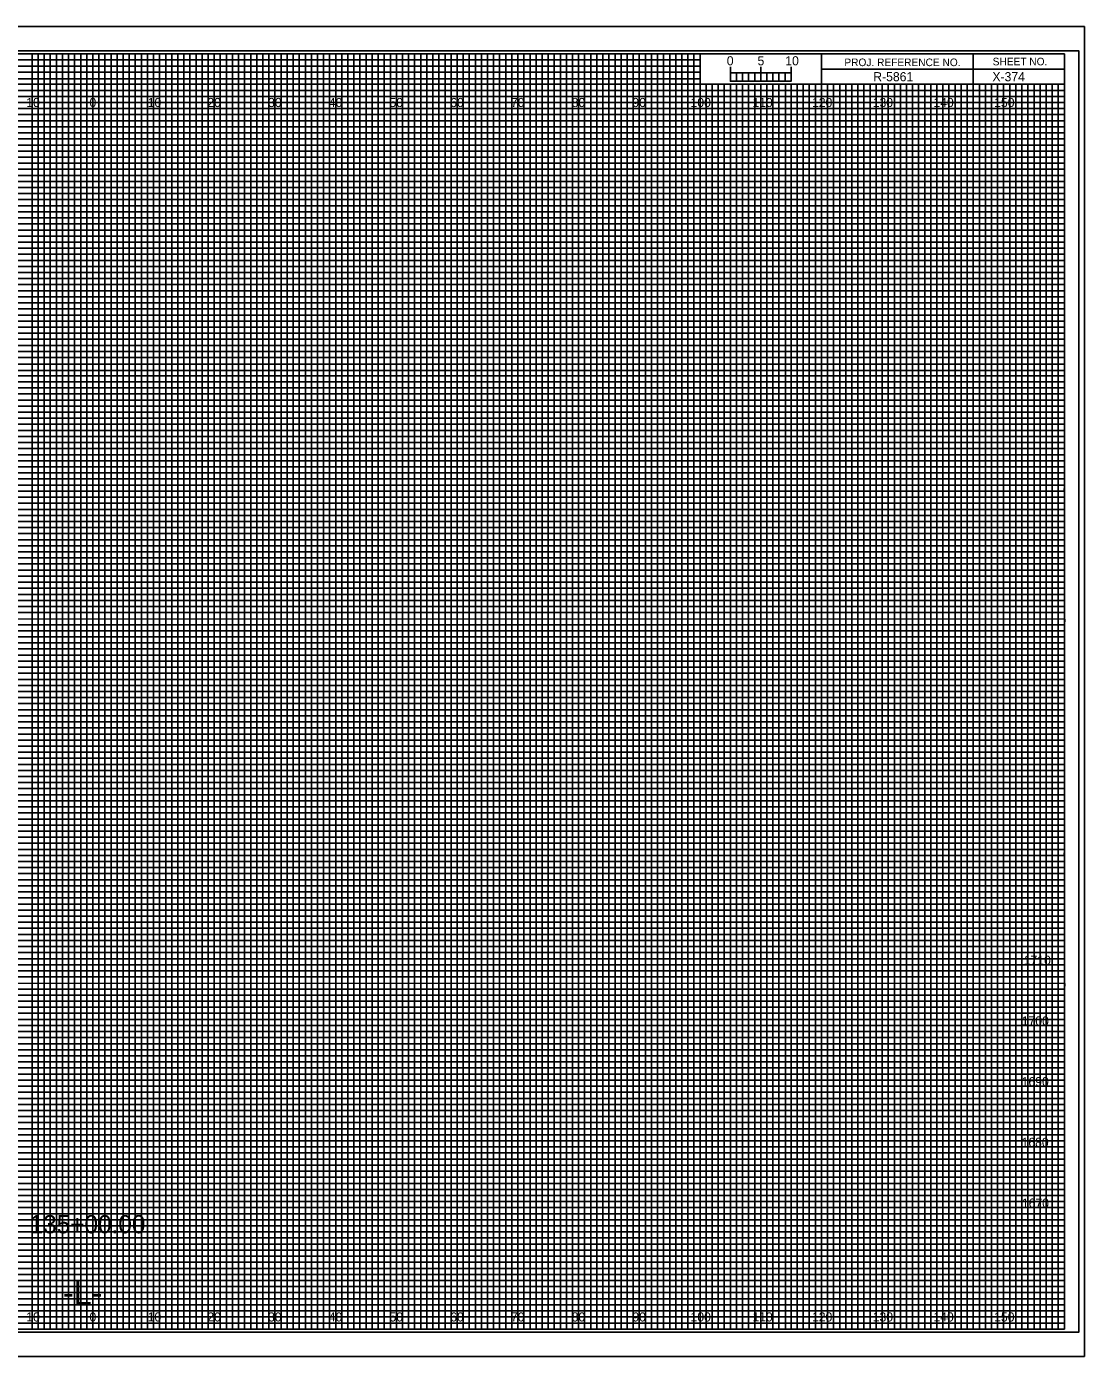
# Model space of a CAD drawing. Extents: x -13 to 323, y -5 to 2414.
# Drawn here: x 149.1 to 323.3, y 2195.5 to 2414.5 of the extents above; entities that cross this region are included whole.
import ezdxf

# ---------------------------------------------------------------- set-up
doc = ezdxf.new("R2010")
doc.units = 0
for name, color, linetype in [('Prop XS Alignment Label', 7, 'Continuous'), ('Prop XS Bar Scale Labels', 7, 'Continuous'), ('Prop XS Elevation Labels', 7, 'Continuous'), ('Prop XS Offset Labels', 7, 'Continuous'), ('Prop XS Project Number', 7, 'Continuous'), ('Prop XS Sheet Number', 7, 'Continuous'), ('Prop XS Station Labels', 7, 'Continuous'), ('Sheet Cross Section CELL', 7, 'Continuous'), ('Sheet Cross Section Grid Major CELL', 7, 'Continuous'), ('Sheet Cross Section Grid Middle CELL', 7, 'Continuous'), ('Sheet Cross Section Grid Minor 1 CELL', 7, 'Continuous'), ('Sheet Cross Section Grid Minor 2 CELL', 7, 'Continuous'), ('Sheet Cross Section Scale CELL', 7, 'Continuous'), ('Sheet Cutting Line CELL', 7, 'Continuous'), ('Sheet DOT Grid CELL', 7, 'Continuous'), ('Sheet Plot Border Inside CELL', 7, 'Continuous'), ('Sheet Plot Border Outside CELL', 7, 'Continuous')]:
    doc.layers.add(name, color=color, linetype=linetype)

msp = doc.modelspace()

# ---------------------------------------------------------------- linework, layer by layer
at = {"layer": 'Sheet Cross Section CELL'}
for p, q in [((305, 2410), (305, 2405)), ((305, 2405), (305, 2410)), ((280, 2407.5), (280, 2405)), ((320, 2407.49), (280, 2407.49)), ((280, 2405), (320, 2405))]:
    msp.add_line(p, q, dxfattribs=at)
for points in [[(320, 2410), (0, 2410), (0, 2200), (320, 2200)], [(280, 2410), (260, 2410), (260, 2405.03), (280, 2405.03)], [(320, 2410), (280, 2410), (280, 2405), (320, 2405)]]:
    msp.add_lwpolyline(points, close=True, dxfattribs=at)
at = {"layer": 'Sheet Cross Section Grid Major CELL'}
for p, q in [((150, 2410), (140, 2410)), ((150, 2200), (150, 2410)), ((170, 2410), (160, 2410)), ((160, 2410), (160, 2200)), ((170, 2200), (170, 2410)), ((190, 2410), (180, 2410)), ((180, 2410), (180, 2200)), ((190, 2200), (190, 2410)), ((210, 2410), (200, 2410)), ((200, 2410), (200, 2200)), ((210, 2200), (210, 2410)), ((230, 2410), (220, 2410)), ((220, 2410), (220, 2200)), ((230, 2200), (230, 2410)), ((250, 2410), (240, 2410)), ((240, 2410), (240, 2200)), ((250, 2200), (250, 2410)), ((260, 2410), (260, 2200)), ((270, 2200), (270, 2405)), ((290, 2405), (280, 2405)), ((280, 2405), (280, 2200)), ((290, 2200), (290, 2405)), ((310, 2405), (300, 2405)), ((300, 2405), (300, 2200)), ((310, 2200), (310, 2405)), ((160, 2200), (150, 2200)), ((180, 2200), (170, 2200)), ((200, 2200), (190, 2200)), ((220, 2200), (210, 2200)), ((240, 2200), (230, 2200)), ((260, 2200), (250, 2200)), ((280, 2200), (270, 2200)), ((300, 2200), (290, 2200)), ((320, 2200), (310, 2200)), ((320, 2200), (320, 2200))]:
    msp.add_line(p, q, dxfattribs=at)
for points in [[(0, 2400), (320, 2400), (320, 2390), (0, 2390)], [(0, 2380), (320, 2380), (320, 2370), (0, 2370)], [(0, 2360), (320, 2360), (320, 2350), (0, 2350)], [(0, 2340), (320, 2340), (320, 2330), (0, 2330)], [(0, 2320), (320, 2320), (320, 2310), (0, 2310)], [(0, 2300), (320, 2300), (320, 2290), (0, 2290)], [(0, 2280), (320, 2280), (320, 2270), (0, 2270)], [(0, 2260), (320, 2260), (320, 2250), (0, 2250)], [(0, 2240), (320, 2240), (320, 2230), (0, 2230)], [(0, 2220), (320, 2220), (320, 2210), (0, 2210)]]:
    msp.add_lwpolyline(points, dxfattribs=at)
at = {"layer": 'Sheet Cross Section Grid Middle CELL'}
for points in [[(145, 2200), (155, 2200), (155, 2410), (165, 2410), (165, 2200), (175, 2200), (175, 2410), (185, 2410), (185, 2200), (195, 2200), (195, 2410), (205, 2410), (205, 2200), (215, 2200), (215, 2410), (225, 2410), (225, 2200), (235, 2200), (235, 2410), (245, 2410), (245, 2200), (255, 2200), (255, 2410), (259.93, 2410), (260, 2410), (260, 2405), (264.99, 2405), (264.99, 2200), (275, 2200), (275, 2405), (285, 2405), (285, 2200), (295, 2200), (295, 2405), (305, 2405), (305, 2200), (315, 2200), (315, 2405)], [(0, 2405), (275, 2405)], [(0, 2385), (320, 2385), (320, 2395), (0, 2395)], [(0, 2365), (320, 2365), (320, 2375), (0, 2375)], [(0, 2345), (320, 2345), (320, 2355), (0, 2355)], [(0, 2325), (320, 2325), (320, 2335), (0, 2335)], [(0, 2305), (320, 2305), (320, 2315), (0, 2315)], [(0, 2285), (320, 2285), (320, 2295), (0, 2295)], [(0, 2265), (320, 2265), (320, 2275), (0, 2275)], [(0, 2245), (320, 2245), (320, 2255), (0, 2255)], [(0, 2225), (320, 2225), (320, 2235), (0, 2235)], [(0, 2205), (320, 2205), (320, 2215), (0, 2215)]]:
    msp.add_lwpolyline(points, dxfattribs=at)
at = {"layer": 'Sheet Cross Section Grid Minor 1 CELL'}
for p, q in [((0, 2409), (260, 2409)), ((260, 2409), (260, 2407.98)), ((260, 2407.98), (0, 2407.98)), ((0, 2407), (260, 2407)), ((260, 2407), (260, 2405.89)), ((260, 2405.89), (0, 2405.89)), ((0, 2404), (320, 2404))]:
    msp.add_line(p, q, dxfattribs=at)
for points in [[(0, 2403), (270, 2403), (320, 2403), (320, 2402), (0, 2402)], [(0, 2401), (320, 2401), (320, 2399), (0, 2399)], [(0, 2398), (320, 2398), (320, 2397), (0, 2396.98)], [(0, 2396), (320, 2396), (320, 2394), (0, 2394)], [(0, 2393), (320, 2393), (320, 2392), (0, 2392)], [(0, 2391), (320, 2391), (320, 2389), (0, 2389)], [(0, 2388), (320, 2388), (320, 2387), (0, 2387)], [(0, 2386), (320, 2386), (320, 2384), (0, 2384)], [(0, 2383), (320, 2383), (320, 2382), (0, 2382)], [(0, 2381), (320, 2381), (320, 2379), (0, 2379)], [(0, 2378), (320, 2378), (320, 2377), (0, 2377)], [(0, 2376), (320, 2376), (320, 2373.95), (320, 2373), (320, 2372), (0, 2372)], [(0, 2374), (320, 2374), (320, 2373), (0, 2373)], [(0, 2371), (320, 2371), (320, 2369), (0, 2369.03)], [(0, 2369.03), (320, 2369), (320, 2368), (0, 2368)], [(0, 2367), (320, 2367), (320, 2366), (0, 2366)], [(0, 2364), (320, 2364), (320, 2363), (0, 2363)], [(0, 2362), (320, 2362), (320, 2361), (0, 2361)], [(-0.07, 2358.89), (320, 2358.89), (320, 2357.88), (-0.07, 2357.88)], [(0, 2357), (320, 2357), (320, 2356), (0, 2356)], [(0, 2354), (320, 2354), (320, 2353), (0, 2353)], [(0, 2352), (320, 2352), (320, 2351), (0, 2351)], [(0, 2349), (320, 2349), (320, 2348), (0, 2348)], [(0, 2347), (320, 2347), (320, 2346), (0, 2346)], [(0, 2344), (320, 2344), (320, 2343), (0, 2343)], [(0, 2342), (320, 2342), (320, 2341), (0, 2341)], [(0, 2339), (320, 2339), (319.99, 2337.98), (0, 2338)], [(0, 2337), (320, 2337), (320, 2336), (0, 2336)], [(0, 2334), (320, 2334), (320, 2333), (0, 2333)], [(0, 2332), (320, 2332), (320, 2331), (0, 2331)], [(0, 2329), (320, 2329), (320, 2328), (0, 2328)], [(0, 2327), (320, 2327), (320, 2326), (0, 2326)], [(0, 2324), (320, 2324), (320, 2323), (0, 2323)], [(0, 2322), (320, 2322), (320, 2321), (0, 2321)], [(0, 2319), (320, 2319), (320, 2318), (0, 2318)], [(0, 2316.99), (320.07, 2316.91), (320, 2316), (0, 2316)], [(0, 2314), (320, 2314), (320, 2313), (0, 2313)], [(0, 2312), (320, 2312), (320, 2311), (0, 2311)], [(0, 2309), (320, 2309), (320, 2308), (0, 2308)], [(0, 2307), (320, 2307), (320, 2306), (0, 2306)], [(0, 2304), (320, 2304), (320, 2303), (0, 2303)], [(0, 2302), (320, 2302), (320, 2301), (0, 2301)], [(0, 2299), (320, 2299), (320, 2298), (0, 2298)], [(0, 2297), (320, 2297), (320, 2296), (0, 2296)], [(0, 2294), (320, 2294), (320, 2293), (0, 2293)], [(0, 2292), (320, 2292), (320, 2291), (0, 2291)], [(0, 2289), (320, 2289), (320, 2288), (0, 2288)], [(0, 2287), (320, 2287), (320, 2286), (0, 2286)], [(0, 2284), (320, 2284), (320, 2283), (0, 2283)], [(0, 2282), (320, 2282), (320, 2281), (0, 2281)], [(0, 2279), (320, 2279), (319.99, 2277.98), (0, 2278)], [(0, 2277), (320, 2277), (320, 2276), (0, 2276)], [(0, 2274), (320, 2274), (320, 2273), (0, 2273)], [(0, 2272), (320, 2272), (320, 2271), (0, 2271)], [(0, 2269), (320, 2269), (320, 2268), (0, 2268)], [(0, 2267), (320, 2267), (320, 2266), (0, 2266)], [(0, 2264), (320, 2264), (320, 2263), (0, 2263)], [(0, 2262), (320, 2262), (320, 2261), (0, 2261)], [(0, 2259), (320, 2259), (320, 2258), (0, 2258)], [(0, 2256.99), (320.07, 2256.91), (320, 2256), (0, 2256)], [(0, 2254), (320, 2254), (320, 2253), (0, 2253)], [(0, 2252), (320, 2252), (320, 2251), (0, 2251)], [(0, 2249), (320, 2249), (320, 2248), (0, 2248)], [(0, 2247), (320, 2247), (320, 2246), (0, 2246)], [(0, 2244), (320, 2244), (320, 2243), (0, 2243)], [(0, 2242), (320, 2242), (320, 2241), (0, 2241)], [(0, 2239), (320, 2239), (320, 2238), (0, 2238)], [(0, 2237), (320, 2237), (320, 2236), (0, 2236)], [(0, 2234), (320, 2234), (320, 2233), (0, 2233)], [(0, 2232), (320, 2232), (320, 2231), (0, 2231)], [(0, 2229), (320, 2229), (320, 2228), (0, 2228)], [(0, 2227), (320, 2227), (320, 2226), (0, 2226)], [(0, 2224), (320, 2224), (320, 2223), (0, 2223)], [(0, 2222), (320, 2222), (320, 2221), (0, 2221)], [(0, 2219), (320, 2219), (320, 2218), (0, 2218)], [(0, 2217), (320, 2217), (320, 2216), (0, 2216)], [(0, 2214), (320, 2214), (320, 2213), (0, 2213)], [(0, 2212), (320, 2212), (320, 2211), (0, 2211)], [(0, 2209), (320, 2209), (320, 2208), (0, 2208)], [(0, 2207), (320, 2207), (320, 2206), (0, 2206)], [(0, 2204), (320, 2204), (320, 2203), (0, 2203)], [(0, 2202), (320, 2202), (320, 2201), (0, 2201)]]:
    msp.add_lwpolyline(points, dxfattribs=at)
at = {"layer": 'Sheet Cross Section Grid Minor 2 CELL'}
for p, q in [((267, 2405), (266.01, 2405)), ((266.01, 2405), (266.01, 2200)), ((267, 2200), (267, 2405)), ((269, 2405), (268, 2405)), ((268, 2405), (268, 2200)), ((269, 2200), (269, 2405)), ((266.01, 2200), (265, 2200)), ((268, 2200), (267, 2200))]:
    msp.add_line(p, q, dxfattribs=at)
for points in [[(150, 2200), (151, 2200), (151, 2410), (152, 2410), (152, 2200)], [(152, 2200), (153, 2200), (153, 2410), (154, 2410), (154, 2200)], [(155, 2200), (156, 2200), (156, 2410), (157, 2410), (157, 2200)], [(157, 2200), (158, 2200), (158, 2410), (159, 2410), (159, 2200)], [(160, 2200), (161, 2200), (161, 2410), (162, 2410), (162, 2200)], [(162, 2200), (163, 2200), (163, 2410), (164, 2410), (164, 2200)], [(165, 2200), (166, 2200), (166, 2410), (167, 2410), (167, 2200)], [(167, 2200), (168, 2200), (168, 2410), (169, 2410), (169, 2200)], [(170, 2200), (171, 2200), (171, 2410), (172, 2410), (172, 2200)], [(172, 2200), (173, 2200), (173, 2410), (174, 2410), (174, 2200)], [(175, 2200), (176, 2200), (176, 2410), (177, 2410), (177, 2200)], [(177, 2200), (178, 2200), (178, 2410), (179, 2410), (179, 2200)], [(180, 2200), (181, 2200), (181, 2410), (182, 2410), (182, 2200)], [(182, 2200), (183, 2200), (183, 2410), (184, 2410), (184, 2200)], [(185, 2200), (186, 2200), (186, 2410), (187, 2410), (187, 2200)], [(187, 2200), (188, 2200), (188, 2410), (189, 2410), (189, 2200)], [(190, 2200), (191, 2200), (191, 2410), (192, 2410), (192, 2200)], [(192, 2200), (193, 2200), (193, 2410), (194, 2410), (194, 2200)], [(195, 2200), (196, 2200), (196, 2410), (197, 2410), (197, 2200)], [(197, 2200), (198, 2200), (198, 2410), (199, 2410), (199, 2200)], [(200, 2200), (201, 2200), (201, 2410), (202, 2410), (202, 2200)], [(202, 2200), (203, 2200), (203, 2410), (204, 2410), (204, 2200)], [(205, 2200), (206, 2200), (206, 2410), (207, 2410), (207, 2200)], [(207, 2200), (208, 2200), (208, 2410), (209, 2410), (209, 2200)], [(210, 2200), (211, 2200), (211, 2410), (212, 2410), (212, 2200)], [(212, 2200), (213, 2200), (213, 2410), (214, 2410), (214, 2200)], [(215, 2200), (216, 2200), (216, 2410), (217, 2410), (217, 2200)], [(217, 2200), (218, 2200), (218, 2410), (219, 2410), (219, 2200)], [(220, 2200), (221, 2200), (221, 2410), (222, 2410), (222, 2200)], [(222, 2200), (223, 2200), (223, 2410), (224, 2410), (224, 2200)], [(225, 2200), (226, 2200), (226, 2410), (227, 2410), (227, 2200)], [(227, 2200), (228, 2200), (228, 2410), (229, 2410), (229, 2200)], [(230, 2200), (231, 2200), (231, 2410), (232, 2410), (232, 2200)], [(232, 2200), (233, 2200), (233, 2410), (234, 2410), (234, 2200)], [(235, 2200), (236, 2200), (236, 2410), (237, 2410), (237, 2200)], [(237, 2200), (238, 2200), (238, 2410), (239, 2410), (239, 2200)], [(240, 2200), (241, 2200), (241, 2410), (242, 2410), (242, 2200)], [(242, 2200), (243, 2200), (243, 2410), (244, 2410), (244, 2200)], [(245, 2200), (246, 2200), (246, 2410), (247, 2410), (247, 2200)], [(247, 2200), (248, 2200), (248, 2410), (249, 2410), (249, 2200)], [(250, 2200), (251, 2200), (251, 2410), (252, 2410), (252, 2200)], [(252, 2200), (253, 2200), (253, 2410), (254, 2410), (254, 2200)], [(255, 2200), (256, 2200), (256, 2410), (257, 2410), (257, 2200)], [(257, 2200), (258, 2200), (258, 2410), (259, 2410), (259, 2200)], [(260, 2200), (261, 2200), (261, 2405), (262.02, 2405), (262.02, 2200)], [(262, 2200), (263, 2200), (263, 2405), (263.99, 2405), (263.99, 2200)], [(270, 2200), (270.98, 2200), (270.98, 2405), (272, 2405), (272, 2200)], [(272, 2200), (273, 2200), (273, 2405), (274.05, 2405), (274.05, 2200)], [(275, 2200), (276, 2200), (276, 2405), (277, 2405), (277, 2200)], [(277, 2200), (278, 2200), (278, 2405), (279, 2405), (279, 2200)], [(280, 2200), (281, 2200), (281, 2405), (282, 2405), (282, 2200)], [(282, 2200), (283, 2200), (283, 2405), (284, 2405), (284, 2200)], [(285, 2200), (286, 2200), (286, 2405), (287, 2405), (287, 2200)], [(287, 2200), (288, 2200), (288, 2405), (289, 2405), (289, 2200)], [(290, 2200), (291, 2200), (291, 2405), (292, 2405), (292, 2200)], [(292, 2200), (293, 2200), (293, 2405), (294, 2405), (294, 2200)], [(295, 2200), (296, 2200), (296, 2405), (297, 2405), (297, 2200)], [(297, 2200), (298, 2200), (298, 2405), (299, 2405), (299, 2200)], [(300, 2200), (301, 2200), (301, 2405), (302, 2405), (302, 2200)], [(302, 2200), (303, 2200), (303, 2405), (304, 2405), (304, 2200)], [(305, 2200), (306, 2200), (306, 2405), (307, 2405), (307, 2200)], [(307, 2200), (308, 2200), (308, 2405), (309, 2405), (309, 2200)], [(310, 2200), (311, 2200), (311, 2405), (312, 2405), (312, 2200)], [(312, 2200), (313, 2200), (313, 2405), (314, 2405), (314, 2200)], [(315, 2200), (316, 2200), (316, 2405), (317, 2405), (317, 2200)], [(317, 2200), (318, 2200), (318, 2405), (319, 2405), (319, 2200)]]:
    msp.add_lwpolyline(points, dxfattribs=at)
at = {"layer": 'Sheet Cross Section Scale CELL'}
for p, q in [((265, 2405.49), (265, 2407.9)), ((265, 2406.9), (265, 2407.9)), ((270, 2405.49), (270, 2407.9)), ((275, 2405.49), (275, 2407.9)), ((275, 2406.9), (275, 2407.9))]:
    msp.add_line(p, q, dxfattribs=at)
for points in [[(275, 2406.9), (265, 2406.9), (265, 2405.49), (275, 2405.49)], [(265, 2406.9), (266, 2406.9), (266, 2405.49), (265, 2405.49)], [(267, 2406.9), (268, 2406.9), (268, 2405.49), (267, 2405.49)], [(269, 2406.9), (270, 2406.9), (270, 2405.49), (269, 2405.49)], [(271, 2406.9), (272, 2406.9), (272, 2405.49), (271, 2405.49)], [(273, 2406.9), (274, 2406.9), (274, 2405.49), (273, 2405.49)]]:
    msp.add_lwpolyline(points, close=True, dxfattribs=at)
at = {"layer": 'Sheet Cutting Line CELL'}
for p, q in [((323.3, 2414.5), (-13.4, 2414.5)), ((-13.4, 2195.5), (323.3, 2195.5))]:
    msp.add_line(p, q, dxfattribs=at)
at = {"layer": 'Sheet DOT Grid CELL'}
for p, q in [((150, 2200), (150, 2410)), ((160, 2200), (160, 2410)), ((170, 2200), (170, 2410)), ((180, 2200), (180, 2410)), ((190, 2200), (190, 2410)), ((200, 2200), (200, 2410)), ((210, 2200), (210, 2410)), ((220, 2200), (220, 2410)), ((230, 2200), (230, 2410)), ((240, 2200), (240, 2410)), ((250, 2200), (250, 2410)), ((260, 2200), (260, 2404.69)), ((270, 2200), (270, 2404.69)), ((280, 2200), (280, 2404.69)), ((290, 2200), (290, 2404.69)), ((300, 2200), (300, 2404.69)), ((310, 2200), (310, 2404.69)), ((0, 2400), (320, 2400)), ((0, 2390), (320, 2390)), ((0, 2380), (320, 2380)), ((0, 2370), (320, 2370)), ((0, 2360), (320, 2360)), ((0, 2350), (320, 2350)), ((0, 2340), (320, 2340)), ((0, 2330), (320, 2330)), ((0, 2320), (320, 2320)), ((0, 2310), (320, 2310)), ((0, 2300), (320, 2300)), ((0, 2290), (320, 2290)), ((0, 2280), (320, 2280)), ((0, 2270), (320, 2270)), ((0, 2260), (320, 2260)), ((0, 2250), (320, 2250)), ((0, 2240), (320, 2240)), ((0, 2230), (320, 2230)), ((0, 2220), (320, 2220)), ((0, 2210), (320, 2210))]:
    msp.add_line(p, q, dxfattribs=at)
at = {"layer": 'Sheet Plot Border Inside CELL'}
msp.add_lwpolyline([(-10.8, 2199.5), (322.4, 2199.5), (322.4, 2410.5), (-10.8, 2410.5)], close=True, dxfattribs=at)
at = {"layer": 'Sheet Plot Border Outside CELL'}
msp.add_lwpolyline([(-13.4, 2195.5), (323.3, 2195.5), (323.3, 2414.5), (-13.4, 2414.5)], close=True, dxfattribs=at)

# ---------------------------------------------------------------- texts
at = {"layer": 'Prop XS Alignment Label'}
msp.add_text('-L-', height=4, dxfattribs=at).set_placement((155.06, 2204))
at = {"layer": 'Prop XS Bar Scale Labels'}
for s, p in [('5', (269.47, 2408.12)), ('10', (274.04, 2408.12))]:
    msp.add_text(s, height=1.5, dxfattribs=at).set_placement(p)
at = {"layer": 'Prop XS Elevation Labels'}
for s, p in [('1710', (313.31, 2260)), ('1700', (312.98, 2250)), ('1690', (312.97, 2240)), ('1680', (312.95, 2230)), ('1670', (313, 2220))]:
    msp.add_text(s, height=1.5, dxfattribs=at).set_placement(p)
at = {"layer": 'Prop XS Offset Labels'}
for s, p in [('10', (149.04, 2401.25)), ('0', (159.45, 2401.25)), ('0', (159.45, 2401.25)), ('10', (169.04, 2401.25)), ('20', (178.86, 2401.25)), ('30', (188.86, 2401.25)), ('40', (198.86, 2401.25)), ('50', (208.86, 2401.25)), ('60', (218.86, 2401.25)), ('70', (228.86, 2401.25)), ('80', (238.86, 2401.25)), ('90', (248.86, 2401.25)), ('100', (258.44, 2401.25)), ('110', (268.62, 2401.25)), ('120', (278.44, 2401.25)), ('130', (288.44, 2401.25)), ('140', (298.44, 2401.25)), ('150', (308.44, 2401.25)), ('10', (149.04, 2201.25)), ('0', (159.45, 2201.25)), ('0', (159.45, 2201.25)), ('10', (169.04, 2201.25)), ('20', (178.86, 2201.25)), ('30', (188.86, 2201.25)), ('40', (198.86, 2201.25)), ('50', (208.86, 2201.25)), ('60', (218.86, 2201.25)), ('70', (228.86, 2201.25)), ('80', (238.86, 2201.25)), ('90', (248.86, 2201.25)), ('100', (258.44, 2201.25)), ('110', (268.62, 2201.25)), ('120', (278.44, 2201.25)), ('130', (288.44, 2201.25)), ('140', (298.44, 2201.25)), ('150', (308.44, 2201.25))]:
    msp.add_text(s, height=1.5, dxfattribs=at).set_placement(p)
at = {"layer": 'Prop XS Project Number'}
msp.add_text('R-5861', height=1.5, dxfattribs=at).set_placement((288.53, 2405.5))
at = {"layer": 'Prop XS Sheet Number'}
msp.add_text('X-374', height=1.5, dxfattribs=at).set_placement((308.15, 2405.5))
at = {"layer": 'Prop XS Station Labels'}
msp.add_text('135+00.00', height=3, dxfattribs=at).set_placement((149.59, 2215.77))
at = {"layer": 'Sheet Cross Section CELL'}
for s, p in [('PROJ. REFERENCE NO.', (283.77, 2407.99)), ('SHEET NO.', (308.19, 2408.12))]:
    msp.add_text(s, height=1.25, dxfattribs=at).set_placement(p)
at = {"layer": 'Sheet Cross Section Scale CELL'}
msp.add_text('0', height=1.5, dxfattribs=at).set_placement((264.41, 2408.12))

doc.saveas('drawing.dxf')
